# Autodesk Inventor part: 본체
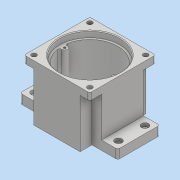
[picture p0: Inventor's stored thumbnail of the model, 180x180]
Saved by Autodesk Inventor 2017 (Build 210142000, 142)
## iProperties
Part Number: 본체
Material: 일반
Document SubType Name: Modeling
Designer: user
Density: 1 g/cm^3
Appearance: 기본값
Author: user
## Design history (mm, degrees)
sketch "스케치1"
  geometry: L1 (-70, -30)-(70, -30); L2 (70, -30)-(70, 30); L3 (70, 30)-(-70, 30); L4 (-70, 30)-(-70, -30); L5 (-70, -30)-(70, 30); L6 (70, -30)-(-70, 30); L7 (-33, -47)-(33, -47); L8 (33, -47)-(33, 47); L9 (33, 47)-(-33, 47); L10 (-33, 47)-(-33, -47); L11 (-33, -47)-(33, 47); L12 (33, -47)-(-33, 47); 1 further point
  constraints: 24 end point, 4 midpoint, 4 parallel, 2 horizontal, 2 perpendicular
  dimensions: "d0" = 66 distance of L8.end L9.end; "d1" = 60 distance of L1.end L2.end; "d2" = 140 distance of L1.start L1.end; "d3" = 94 distance between parallel lines of L9 L7
extrude "돌출1" new body sketch "스케치1" distance "d4" = 13; taper "d5" = 0 deg
sketch "스케치2"
  geometry: L1 (-33, 47)-(33, 47); L2 (33, 47)-(33, -47); L3 (33, -47)-(-33, -47); L4 (-33, -47)-(-33, 47); L5 (-33, 47)-(33, -47); L6 (33, 47)-(-33, -47); L7 (-47, -30)-(47, -30); L8 (47, -30)-(47, 30); L9 (47, 30)-(-47, 30); L10 (-47, 30)-(-47, -30); L11 (-47, -30)-(47, 30); L12 (47, -30)-(-47, 30); 3 further points
  constraints: 24 end point, 5 midpoint, 4 parallel, 2 horizontal, 2 perpendicular, 1 coincident
  dimensions: "d6" = 66 distance of L1.start L1.end; "d7" = 94 distance of L1.end L2.end; "d8" = 94 distance of L8.end L9.end; "d9" = 60 distance of L7.end L8.end
extrude "돌출2" join sketch "스케치2" distance "d10" = 57; taper "d11" = 0 deg
sketch "스케치3"
  geometry: L1 (-47, -47)-(47, -47); L2 (47, -47)-(47, 47); L3 (47, 47)-(-47, 47); L4 (-47, 47)-(-47, -47); L5 (-47, -47)-(47, 47); L6 (47, -47)-(-47, 47); 3 further points
  constraints: 12 end point, 3 midpoint, 2 parallel, 1 coincident, 1 horizontal, 1 perpendicular
  dimensions: "d12" = 94 distance of L2.end L3.end; "d13" = 94 distance of L1.end L2.end
extrude "돌출3" join sketch "스케치3" distance "d14" = 10; taper "d15" = 0 deg
sketch "스케치4"
  geometry: L1 (-40, -40)-(40, -40); L2 (40, -40)-(40, 40); L3 (40, 40)-(-40, 40); L4 (-40, 40)-(-40, -40); L5 (-40, -40)-(40, 40); L6 (40, -40)-(-40, 40); C1 r 3.5 at (40, 40); C2 r 3.5 at (-40, 40); C3 r 3.5 at (-40, -40); C4 r 3.5 at (40, -40); 1 further point
  constraints: 12 end point, 4 centre point, 3 coincident, 2 midpoint, 2 parallel, 1 horizontal, 1 perpendicular
  dimensions: "d16" = 80 distance of L2.end L3.end; "d17" = 80 distance of L1.end L2.end; "d18" = 7 diameter of C1; "d19" = 7 diameter of C4; "d20" = 7 diameter of C3; "d21" = 7 diameter of C2
extrude "돌출4" cut sketch "스케치4" distance "d22" = 10; taper "d23" = 0 deg
sketch "스케치5"
  geometry: C1 r 43 at (0, 0); 1 further point
  constraints: 1 centre point, 1 coincident
  dimensions: "d24" = 86 diameter of C1
extrude "돌출5" cut sketch "스케치5" distance "d25" = 9; taper "d26" = 0 deg
sketch "스케치6"
  geometry: C1 r 40 at (0, 0); 1 further point
  constraints: 1 centre point, 1 coincident
  dimensions: "d27" = 80 diameter of C1
extrude "돌출6" cut sketch "스케치6" distance "d28" = 62; taper "d29" = 0 deg
sketch "스케치7"
  geometry: C1 r 21 at (0, 11); C2 r 15 at (0, -20); 1 further point
  constraints: 2 centre point
  dimensions: "d30" = 42 diameter of C1; "d31" = 30 diameter of C2; "d32" = 11 distance of point (0, 0) C1.centre; "d33" = 20 distance of C2.centre point (0, 0)
extrude "돌출7" join sketch "스케치7" distance "d34" = 7; taper "d35" = 0 deg
sketch "스케치9"
  geometry: C1 r 27.5 at (0, 11); A1 r 21 centre (0, 11) between (8.978, -7.984) and (-8.978, -7.984) reference; 1 further point
  constraints: 1 centre point, 1 coincident
  dimensions: "d36" = 55 diameter of C1
extrude "돌출8" join sketch "스케치9" distance "d37" = 7; taper "d38" = 0 deg
hole "구멍1" diameter "d41" = 25; stored, may be unused: countersink angle "d45" = 90 deg, drill point angle "d47" = 0 deg; dims "d39" = 10, "d40" = 10, "d42" = 6, "d43" = 35, "d44" = 10, "d46" = 100
hole "구멍2" diameter "d50" = 32; stored, may be unused: countersink angle "d54" = 90 deg, drill point angle "d56" = 0 deg; dims "d48" = 10, "d49" = 10, "d51" = 6, "d52" = 35, "d53" = 10, "d55" = 8.3
hole "구멍3" diameter "d59" = 19; stored, may be unused: countersink angle "d63" = 90 deg, drill point angle "d65" = 0 deg; dims "d57" = 10, "d58" = 10, "d60" = 6, "d61" = 22, "d62" = 7, "d64" = 10
chamfer "모따기1" distance "d66" = 1; stored, may be unused: second distance "d67" = 2, angle "d68" = 45 deg
chamfer "모따기2" distance "d69" = 0.8; stored, may be unused: second distance "d70" = 2, angle "d71" = 30 deg
sketch "스케치10"
  geometry: A1 r 40 centre (0, 0) between (-39.279, 7.559) and (-39.279, -7.559) reference; A2 r 4 centre (-36, 0) between (-36.19, -3.995) and (-36.19, 3.995); A3 r 3 centre (-36.333, 6.992) between (-39.279, 7.559) and (-36.19, 3.995); A4 r 3 centre (-36.333, -6.992) between (-36.19, -3.995) and (-39.279, -7.559); A5 r 40 centre (0, 0) between (-39.279, 7.559) and (-39.279, -7.559); 1 further point
  constraints: 10 point on circle, 6 tangent, 4 centre point, 1 horizontal alignment
  dimensions: "d72" = 8 diameter of A2; "d73" = 36 distance of A2.centre point (0, 0); "d74" = 3 radius of A3; "d75" = 3 radius of A4
extrude "돌출9" join sketch "스케치10" stored distance "d76" = 7; taper "d77" = 0 deg
hole "구멍4" diameter "d80" = 3.242; stored, may be unused: countersink angle "d84" = 90 deg, drill point angle "d86" = 118 deg; dims "d78" = 10, "d79" = 10, "d81" = 7, "d82" = 22, "d83" = 7, "d85" = 9
fillet "모깎기1" dims "d87" = 3
sketch "스케치11"
  geometry: L1 (77, -80)-(-11, -80) reference; L2 (66, 0)-(0, 0) reference; 3 further points
  constraints: 1 midpoint, 1 vertical alignment, 1 other
  dimensions: "d88" = 40 distance from line of L1 point (33, -40)
feature "엠보싱1" sketch "스케치11" dims "d1" = 60, "d2" = 140, "d6" = 66, "d7" = 94, "d8" = 94, "d9" = 60, "d89" = 0.5, "d90" = 0
sketch "스케치12"
  geometry: 3 further points
  constraints: 1 vertical alignment
  dimensions: "d91" = 60 horizontal distance of point (0, 0) point (-60, 19); "d92" = 38 distance of point (-60, -19) point (-60, 19); "d93" = 19 vertical distance of point (0, 0) point (-60, 19)
hole "구멍5" sketch "스케치12" at (-60, 19), (-60, -19) diameter "d94" = 4.5; stored, may be unused: countersink angle "d98" = 90 deg, drill point angle "d100" = 118 deg; dims "d95" = 7, "d96" = 10, "d97" = 5, "d99" = 100
chamfer "모따기3" distance "d101" = 1; stored, may be unused: second distance "d102" = 2, angle "d103" = 30 deg
fillet "모깎기2" dims "d104" = 3
fillet "모깎기3" dims "d105" = 3
node "솔리드1"
mirror "미러1"
mirror "미러2"
